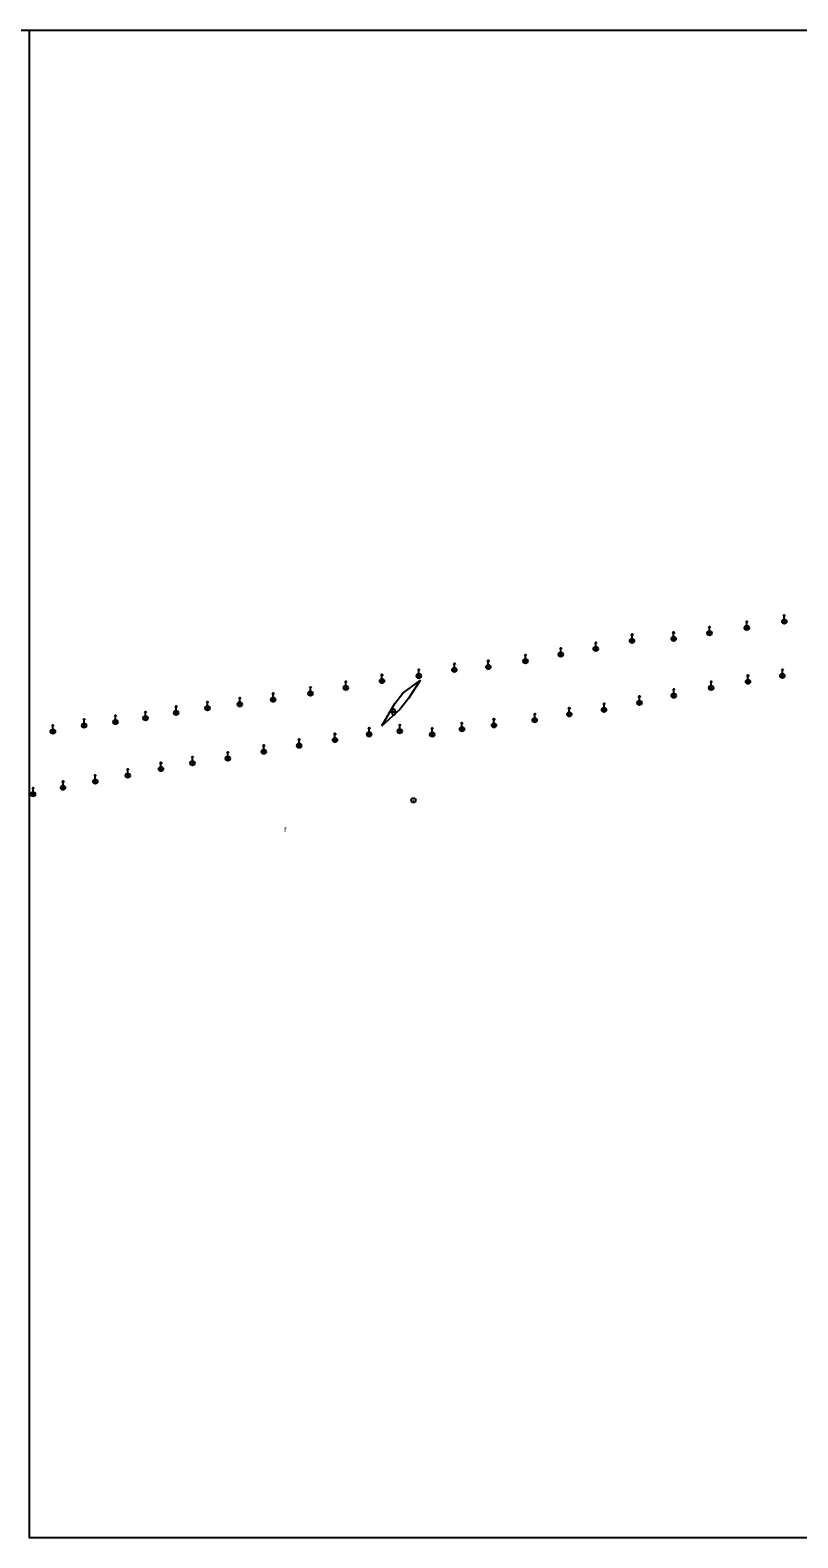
# Model space of a CAD drawing. Extents: x -582188 to -561562, y -1187250 to -1183500.
# Drawn here: x -579062.4 to -578935.1, y -1186500 to -1186250 of the extents above; entities that cross this region are included whole.
import ezdxf

# ---------------------------------------------------------------- set-up
doc = ezdxf.new("R2010")
doc.units = 0
for name, color, linetype in [('MAP_ZN_BP', 7, 'Continuous'), ('RÁMY_ML', 7, 'Continuous'), ('ZELEŇ', 7, 'Continuous'), ('ZN_BP', 7, 'Continuous'), ('ZN_KULTUR', 7, 'Continuous')]:
    doc.layers.add(name, color=color, linetype=linetype)

msp = doc.modelspace()

# ---------------------------------------------------------------- linework, layer by layer
at = {"layer": 'MAP_ZN_BP'}
for radius in [0.375, 0.0005]:
    msp.add_circle((-578998.83, -1186377.711), radius, dxfattribs=at)
at = {"layer": 'RÁMY_ML'}
msp.add_lwpolyline([(-579375, -1186250), (-579062.5, -1186250), (-578750, -1186250), (-578750, -1186500), (-579062.5, -1186500), (-579062.5, -1186250)], dxfattribs=at)
at = {"layer": 'ZELEŇ'}
msp.add_lwpolyline([(-579004.09, -1186365.34), (-579001.91, -1186361.67), (-579000.61, -1186359.96), (-578997.73, -1186357.83), (-578999.68, -1186360.82), (-579001.1, -1186362.66), (-579004.09, -1186365.34)], dxfattribs=at)
at = {"layer": 'ZN_BP'}
for p, q in [((-578937.37, -1186347.685), (-578937.37, -1186346.935)), ((-578955.72, -1186350.545), (-578955.72, -1186349.795)), ((-578950.025, -1186350.254), (-578949.496, -1186349.726)), ((-578949.496, -1186350.258), (-578950.025, -1186349.726)), ((-578949.76, -1186349.615), (-578949.76, -1186348.865)), ((-578943.845, -1186349.364), (-578943.316, -1186348.836)), ((-578943.316, -1186349.368), (-578943.845, -1186348.836)), ((-578943.58, -1186348.725), (-578943.58, -1186347.975)), ((-578937.635, -1186348.324), (-578937.106, -1186347.796)), ((-578937.106, -1186348.328), (-578937.635, -1186347.796)), ((-578974.42, -1186353.155), (-578974.42, -1186352.405)), ((-578968.895, -1186352.854), (-578968.366, -1186352.326)), ((-578968.366, -1186352.858), (-578968.895, -1186352.326)), ((-578968.63, -1186352.215), (-578968.63, -1186351.465)), ((-578962.875, -1186351.514), (-578962.346, -1186350.986)), ((-578962.346, -1186351.518), (-578962.875, -1186350.986)), ((-578962.61, -1186350.875), (-578962.61, -1186350.125)), ((-578955.985, -1186351.184), (-578955.456, -1186350.656)), ((-578955.456, -1186351.188), (-578955.985, -1186350.656)), ((-578992.07, -1186355.705), (-578992.07, -1186354.955)), ((-578986.44, -1186355.235), (-578986.44, -1186354.485)), ((-578980.535, -1186354.894), (-578980.006, -1186354.366)), ((-578980.006, -1186354.898), (-578980.535, -1186354.366)), ((-578980.27, -1186354.255), (-578980.27, -1186353.505)), ((-578974.685, -1186353.794), (-578974.156, -1186353.266)), ((-578974.156, -1186353.798), (-578974.685, -1186353.266)), ((-579004.07, -1186357.555), (-579004.07, -1186356.805)), ((-578998.225, -1186357.344), (-578997.696, -1186356.816)), ((-578997.696, -1186357.348), (-578998.225, -1186356.816)), ((-578997.96, -1186356.705), (-578997.96, -1186355.955)), ((-578992.335, -1186356.344), (-578991.806, -1186355.816)), ((-578991.806, -1186356.348), (-578992.335, -1186355.816)), ((-578986.705, -1186355.874), (-578986.176, -1186355.346)), ((-578986.176, -1186355.878), (-578986.705, -1186355.346)), ((-578943.39, -1186357.655), (-578943.39, -1186356.905)), ((-578937.955, -1186357.324), (-578937.426, -1186356.796)), ((-578937.426, -1186357.328), (-578937.955, -1186356.796)), ((-578937.69, -1186356.685), (-578937.69, -1186355.935)), ((-579022.1, -1186360.635), (-579022.1, -1186359.885)), ((-579016.185, -1186360.264), (-579015.656, -1186359.736)), ((-579015.656, -1186360.268), (-579016.185, -1186359.736)), ((-579015.92, -1186359.625), (-579015.92, -1186358.875)), ((-579010.325, -1186359.324), (-579009.796, -1186358.796)), ((-579009.796, -1186359.328), (-579010.325, -1186358.796)), ((-579010.06, -1186358.685), (-579010.06, -1186357.935)), ((-579004.335, -1186358.194), (-579003.806, -1186357.666)), ((-579003.806, -1186358.198), (-579004.335, -1186357.666)), ((-578955.7, -1186359.965), (-578955.7, -1186359.215)), ((-578949.755, -1186359.314), (-578949.226, -1186358.786)), ((-578949.226, -1186359.318), (-578949.755, -1186358.786)), ((-578949.49, -1186358.675), (-578949.49, -1186357.925)), ((-578943.655, -1186358.294), (-578943.126, -1186357.766)), ((-578943.126, -1186358.298), (-578943.655, -1186357.766)), ((-579038.2, -1186362.815), (-579038.2, -1186362.065)), ((-579033.255, -1186362.694), (-579032.726, -1186362.166)), ((-579032.726, -1186362.698), (-579033.255, -1186362.166)), ((-579032.99, -1186362.055), (-579032.99, -1186361.305)), ((-579027.895, -1186362.044), (-579027.366, -1186361.516)), ((-579027.366, -1186362.048), (-579027.895, -1186361.516)), ((-579027.63, -1186361.405), (-579027.63, -1186360.655)), ((-579022.365, -1186361.274), (-579021.836, -1186360.746)), ((-579021.836, -1186361.278), (-579022.365, -1186360.746)), ((-578973.01, -1186363.065), (-578973.01, -1186362.315)), ((-578967.525, -1186362.964), (-578966.996, -1186362.436)), ((-578966.996, -1186362.968), (-578967.525, -1186362.436)), ((-578967.26, -1186362.325), (-578967.26, -1186361.575)), ((-578961.655, -1186361.794), (-578961.126, -1186361.266)), ((-578961.126, -1186361.798), (-578961.655, -1186361.266)), ((-578961.39, -1186361.155), (-578961.39, -1186360.405)), ((-578955.965, -1186360.604), (-578955.436, -1186360.076)), ((-578955.436, -1186360.608), (-578955.965, -1186360.076)), ((-579053.45, -1186364.935), (-579053.45, -1186364.185)), ((-579048.505, -1186364.974), (-579047.976, -1186364.446)), ((-579047.976, -1186364.978), (-579048.505, -1186364.446)), ((-579048.24, -1186364.335), (-579048.24, -1186363.585)), ((-579043.525, -1186364.354), (-579042.996, -1186363.826)), ((-579042.996, -1186364.358), (-579043.525, -1186363.826)), ((-579043.26, -1186363.715), (-579043.26, -1186362.965)), ((-579038.465, -1186363.454), (-579037.936, -1186362.926)), ((-579037.936, -1186363.458), (-579038.465, -1186362.926)), ((-578990.81, -1186365.535), (-578990.81, -1186364.785)), ((-578985.5, -1186364.905), (-578985.5, -1186364.155)), ((-578979.015, -1186364.674), (-578978.486, -1186364.146)), ((-578978.486, -1186364.678), (-578979.015, -1186364.146)), ((-578978.75, -1186364.035), (-578978.75, -1186363.285)), ((-578973.275, -1186363.704), (-578972.746, -1186363.176)), ((-578972.746, -1186363.708), (-578973.275, -1186363.176)), ((-579058.885, -1186366.554), (-579058.356, -1186366.026)), ((-579058.356, -1186366.558), (-579058.885, -1186366.026)), ((-579058.62, -1186365.915), (-579058.62, -1186365.165)), ((-579053.715, -1186365.574), (-579053.186, -1186365.046)), ((-579053.186, -1186365.578), (-579053.715, -1186365.046)), ((-579012.125, -1186367.974), (-579011.596, -1186367.446)), ((-579011.596, -1186367.978), (-579012.125, -1186367.446)), ((-579011.86, -1186367.335), (-579011.86, -1186366.585)), ((-579006.445, -1186367.034), (-579005.916, -1186366.506)), ((-579005.916, -1186367.038), (-579006.445, -1186366.506)), ((-579006.18, -1186366.395), (-579006.18, -1186365.645)), ((-579001.385, -1186366.514), (-579000.856, -1186365.986)), ((-579000.856, -1186366.518), (-579001.385, -1186365.986)), ((-579001.12, -1186365.875), (-579001.12, -1186365.125)), ((-578996.005, -1186367.054), (-578995.476, -1186366.526)), ((-578995.476, -1186367.058), (-578996.005, -1186366.526)), ((-578995.74, -1186366.415), (-578995.74, -1186365.665)), ((-578991.075, -1186366.174), (-578990.546, -1186365.646)), ((-578990.546, -1186366.178), (-578991.075, -1186365.646)), ((-578985.765, -1186365.544), (-578985.236, -1186365.016)), ((-578985.236, -1186365.548), (-578985.765, -1186365.016)), ((-579029.62, -1186370.395), (-579029.62, -1186369.645)), ((-579023.915, -1186369.894), (-579023.386, -1186369.366)), ((-579023.386, -1186369.898), (-579023.915, -1186369.366)), ((-579023.65, -1186369.255), (-579023.65, -1186368.505)), ((-579018.075, -1186368.914), (-579017.546, -1186368.386)), ((-579017.546, -1186368.918), (-579018.075, -1186368.386)), ((-579017.81, -1186368.275), (-579017.81, -1186367.525)), ((-579046.21, -1186373.225), (-579046.21, -1186372.475)), ((-579040.975, -1186372.784), (-579040.446, -1186372.256)), ((-579040.446, -1186372.788), (-579040.975, -1186372.256)), ((-579040.71, -1186372.145), (-579040.71, -1186371.395)), ((-579035.755, -1186371.814), (-579035.226, -1186371.286)), ((-579035.226, -1186371.818), (-579035.755, -1186371.286)), ((-579035.49, -1186371.175), (-579035.49, -1186370.425)), ((-579029.885, -1186371.034), (-579029.356, -1186370.506)), ((-579029.356, -1186371.038), (-579029.885, -1186370.506)), ((-579056.94, -1186375.225), (-579056.94, -1186374.475)), ((-579051.855, -1186374.844), (-579051.326, -1186374.316)), ((-579051.326, -1186374.848), (-579051.855, -1186374.316)), ((-579051.59, -1186374.205), (-579051.59, -1186373.455)), ((-579046.475, -1186373.864), (-579045.946, -1186373.336)), ((-579045.946, -1186373.868), (-579046.475, -1186373.336)), ((-579062.175, -1186376.954), (-579061.646, -1186376.426)), ((-579061.646, -1186376.958), (-579062.175, -1186376.426)), ((-579061.91, -1186376.315), (-579061.91, -1186375.565)), ((-579057.205, -1186375.864), (-579056.676, -1186375.336)), ((-579056.676, -1186375.868), (-579057.205, -1186375.336))]:
    msp.add_line(p, q, dxfattribs=at)
for points in [[(-578937.495, -1186347.185), (-578937.37, -1186346.935), (-578937.245, -1186347.185)], [(-578955.845, -1186350.045), (-578955.72, -1186349.795), (-578955.595, -1186350.045)], [(-578949.885, -1186349.115), (-578949.76, -1186348.865), (-578949.635, -1186349.115)], [(-578943.705, -1186348.225), (-578943.58, -1186347.975), (-578943.455, -1186348.225)], [(-578974.545, -1186352.655), (-578974.42, -1186352.405), (-578974.295, -1186352.655)], [(-578968.755, -1186351.715), (-578968.63, -1186351.465), (-578968.505, -1186351.715)], [(-578962.735, -1186350.375), (-578962.61, -1186350.125), (-578962.485, -1186350.375)], [(-578992.195, -1186355.205), (-578992.07, -1186354.955), (-578991.945, -1186355.205)], [(-578986.565, -1186354.735), (-578986.44, -1186354.485), (-578986.315, -1186354.735)], [(-578980.395, -1186353.755), (-578980.27, -1186353.505), (-578980.145, -1186353.755)], [(-579004.195, -1186357.055), (-579004.07, -1186356.805), (-579003.945, -1186357.055)], [(-578998.085, -1186356.205), (-578997.96, -1186355.955), (-578997.835, -1186356.205)], [(-578943.515, -1186357.155), (-578943.39, -1186356.905), (-578943.265, -1186357.155)], [(-578937.815, -1186356.185), (-578937.69, -1186355.935), (-578937.565, -1186356.185)], [(-579022.225, -1186360.135), (-579022.1, -1186359.885), (-579021.975, -1186360.135)], [(-579016.045, -1186359.125), (-579015.92, -1186358.875), (-579015.795, -1186359.125)], [(-579010.185, -1186358.185), (-579010.06, -1186357.935), (-579009.935, -1186358.185)], [(-578955.825, -1186359.465), (-578955.7, -1186359.215), (-578955.575, -1186359.465)], [(-578949.615, -1186358.175), (-578949.49, -1186357.925), (-578949.365, -1186358.175)], [(-579038.325, -1186362.315), (-579038.2, -1186362.065), (-579038.075, -1186362.315)], [(-579033.115, -1186361.555), (-579032.99, -1186361.305), (-579032.865, -1186361.555)], [(-579027.755, -1186360.905), (-579027.63, -1186360.655), (-579027.505, -1186360.905)], [(-578973.135, -1186362.565), (-578973.01, -1186362.315), (-578972.885, -1186362.565)], [(-578967.385, -1186361.825), (-578967.26, -1186361.575), (-578967.135, -1186361.825)], [(-578961.515, -1186360.655), (-578961.39, -1186360.405), (-578961.265, -1186360.655)], [(-579053.575, -1186364.435), (-579053.45, -1186364.185), (-579053.325, -1186364.435)], [(-579048.365, -1186363.835), (-579048.24, -1186363.585), (-579048.115, -1186363.835)], [(-579043.385, -1186363.215), (-579043.26, -1186362.965), (-579043.135, -1186363.215)], [(-578990.935, -1186365.035), (-578990.81, -1186364.785), (-578990.685, -1186365.035)], [(-578985.625, -1186364.405), (-578985.5, -1186364.155), (-578985.375, -1186364.405)], [(-578978.875, -1186363.535), (-578978.75, -1186363.285), (-578978.625, -1186363.535)], [(-579058.745, -1186365.415), (-579058.62, -1186365.165), (-579058.495, -1186365.415)], [(-579011.985, -1186366.835), (-579011.86, -1186366.585), (-579011.735, -1186366.835)], [(-579006.305, -1186365.895), (-579006.18, -1186365.645), (-579006.055, -1186365.895)], [(-579001.245, -1186365.375), (-579001.12, -1186365.125), (-579000.995, -1186365.375)], [(-578995.865, -1186365.915), (-578995.74, -1186365.665), (-578995.615, -1186365.915)], [(-579029.745, -1186369.895), (-579029.62, -1186369.645), (-579029.495, -1186369.895)], [(-579023.775, -1186368.755), (-579023.65, -1186368.505), (-579023.525, -1186368.755)], [(-579017.935, -1186367.775), (-579017.81, -1186367.525), (-579017.685, -1186367.775)], [(-579046.335, -1186372.725), (-579046.21, -1186372.475), (-579046.085, -1186372.725)], [(-579040.835, -1186371.645), (-579040.71, -1186371.395), (-579040.585, -1186371.645)], [(-579035.615, -1186370.675), (-579035.49, -1186370.425), (-579035.365, -1186370.675)], [(-579057.065, -1186374.725), (-579056.94, -1186374.475), (-579056.815, -1186374.725)], [(-579051.715, -1186373.705), (-579051.59, -1186373.455), (-579051.465, -1186373.705)], [(-579062.035, -1186375.815), (-579061.91, -1186375.565), (-579061.785, -1186375.815)]]:
    msp.add_lwpolyline(points, dxfattribs=at)
for centre in [(-578949.76, -1186349.99), (-578943.58, -1186349.1), (-578937.37, -1186348.06), (-578968.63, -1186352.59), (-578962.61, -1186351.25), (-578955.72, -1186350.92), (-578980.27, -1186354.63), (-578974.42, -1186353.53), (-578997.96, -1186357.08), (-578992.07, -1186356.08), (-578986.44, -1186355.61), (-578937.69, -1186357.06), (-579015.92, -1186360), (-579010.06, -1186359.06), (-579004.07, -1186357.93), (-578955.7, -1186360.34), (-578949.49, -1186359.05), (-578943.39, -1186358.03), (-579032.99, -1186362.43), (-579027.63, -1186361.78), (-579022.1, -1186361.01), (-578967.26, -1186362.7), (-578961.39, -1186361.53), (-579053.45, -1186365.31), (-579048.24, -1186364.71), (-579043.26, -1186364.09), (-579038.2, -1186363.19), (-578985.5, -1186365.28), (-578978.75, -1186364.41), (-578973.01, -1186363.44), (-579058.62, -1186366.29), (-579011.86, -1186367.71), (-579006.18, -1186366.77), (-579001.12, -1186366.25), (-578995.74, -1186366.79), (-578990.81, -1186365.91), (-579023.65, -1186369.63), (-579017.81, -1186368.65), (-579040.71, -1186372.52), (-579035.49, -1186371.55), (-579029.62, -1186370.77), (-579051.59, -1186374.58), (-579046.21, -1186373.6), (-579061.91, -1186376.69), (-579056.94, -1186375.6)]:
    msp.add_circle(centre, 0.375, dxfattribs=at)
at = {"layer": 'ZN_KULTUR'}
for p, q in [((-579002.61, -1186363.05), (-579001.61, -1186363.05)), ((-579002.36, -1186363.3), (-579002.36, -1186362.8)), ((-579001.86, -1186363.3), (-579001.86, -1186362.8))]:
    msp.add_line(p, q, dxfattribs=at)
for centre, start, end in [((-579002.11, -1186362.8), 0, 179.99999), ((-579002.11, -1186363.3), 179.99999, 359.99999)]:
    msp.add_arc(centre, 0.25, start, end, dxfattribs=at)

# ---------------------------------------------------------------- texts
msp.add_text('r', height=1, dxfattribs=at).set_placement((-579020.278, -1186382.962))

doc.saveas('drawing.dxf')
